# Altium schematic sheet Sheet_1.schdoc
size 456 x 207 mm
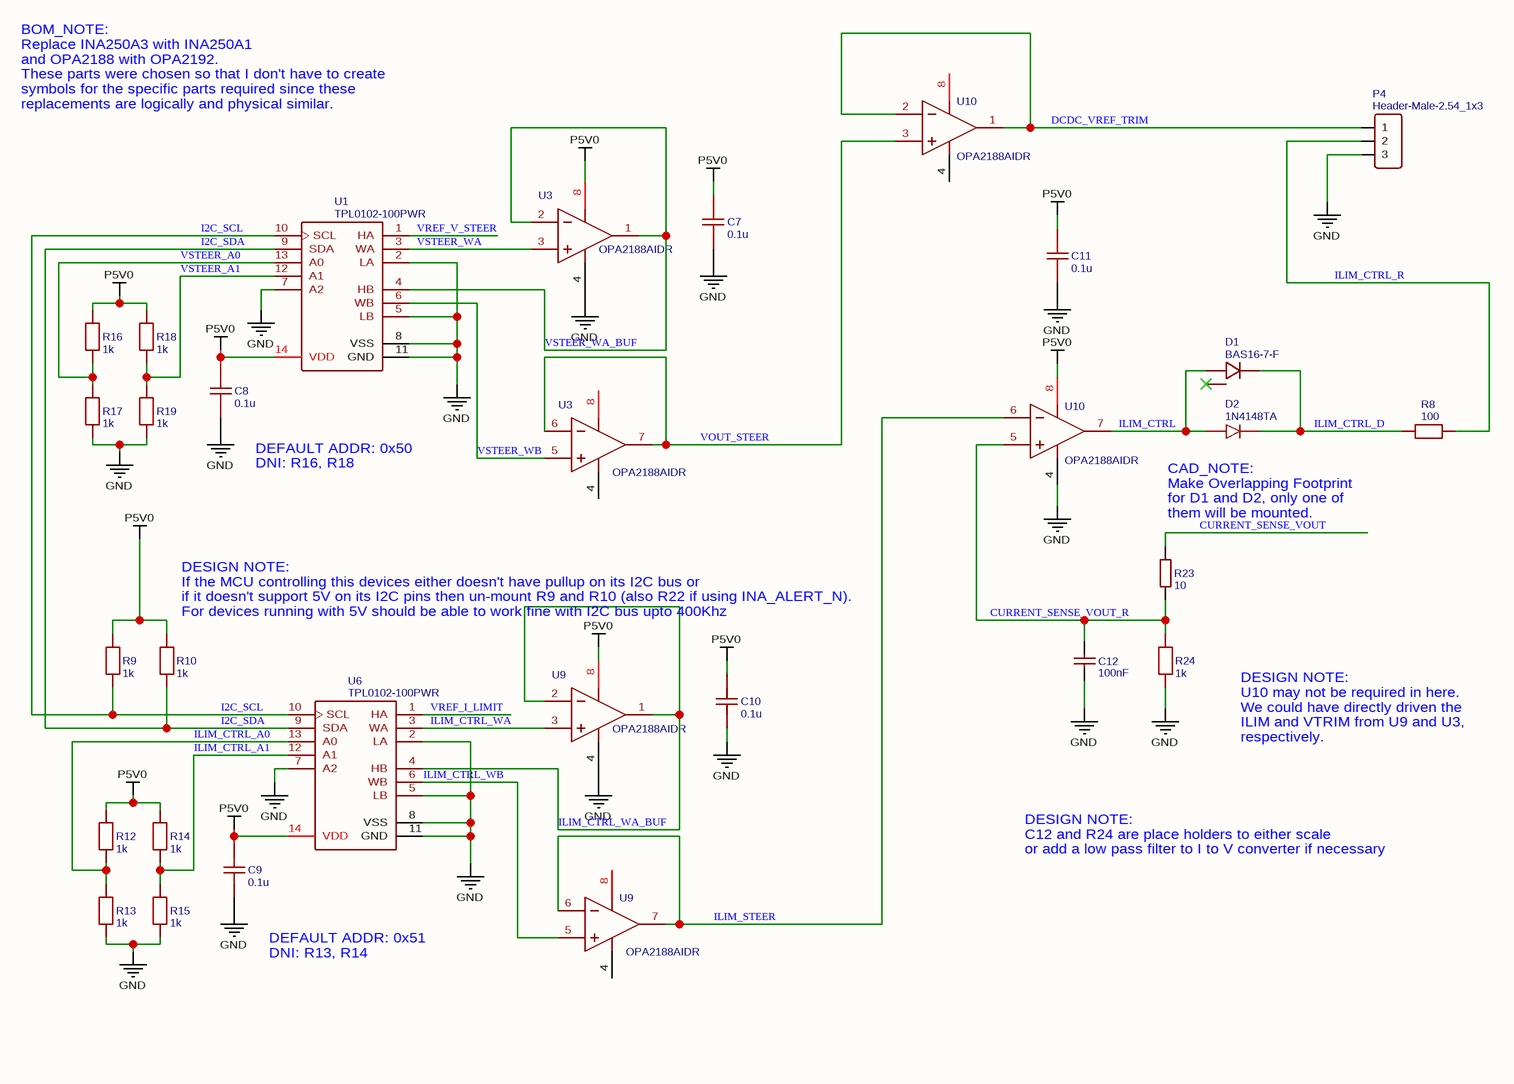
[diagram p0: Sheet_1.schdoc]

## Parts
(Parts that share a designator on the sheet are numbered #1, #2 ... from top to bottom, then left to right.)
C7  0.1u  [0805]
C8  0.1u  [0805]
C9  0.1u  [0805]
C10  0.1u  [0805]
C11  0.1u  [0805]
C12  100nF  [0805]
D1  BAS16-7-F  [SOT-23(SOT-23-3)]
D2  1N4148TA  [DO-35]
P4  Header-Male-2.54_1x3  [HDR-3X1/2.54]
R8  100  [0805]
R9  1k  [0805]
R10  1k  [0805]
R12  1k  [0805]
R13  1k  [0805]
R14  1k  [0805]
R15  1k  [0805]
R16  1k  [0805]
R17  1k  [0805]
R18  1k  [0805]
R19  1k  [0805]
R23  10  [0805]
R24  1k  [0805]
U1  TPL0102-100PWR  [TSSOP-14]
U3#1  OPA2188AIDR  [SOIC-8_150MIL]
U3#2  OPA2188AIDR  [SOIC-8_150MIL]
U6  TPL0102-100PWR  [TSSOP-14]
U9#1  OPA2188AIDR  [SOIC-8_150MIL]
U9#2  OPA2188AIDR  [SOIC-8_150MIL]
U10#1  OPA2188AIDR  [SOIC-8_150MIL]
U10#2  OPA2188AIDR  [SOIC-8_150MIL]

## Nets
GND: C7.1 C8.1 C9.1 C10.1 C11.1 C12.1 P4.3 R13.1 R15.1 R17.1 R19.1 R24.1 U1.2(LA) U1.5(LB) U1.7(A2) U1.8(VSS) U1.11(GND) U3#1.4(V-) U6.2(LA) U6.5(LB) U6.7(A2) U6.8(VSS) U6.11(GND) U9#1.4(V-) U10#2.4(V-)
P5V0: C7.2 C8.2 C9.2 C10.2 C11.2 R9.2 R10.2 R12.2 R14.2 R16.2 R18.2 U1.14(VDD) U3#1.8(V+) U6.14(VDD) U9#1.8(V+) U10#2.8(V+)
CURRENT_SENSE_VOUT: R23.2
CURRENT_SENSE_VOUT_R: C12.2 R23.1 R24.2 U10#2.5(IN_B+)
DCDC_VREF_TRIM: P4.1 U10#1.1(OUT_A) U10#1.2(IN_A-)
I2C_SCL: R9.1 U1.10(SCL) U6.10(SCL)
I2C_SDA: R10.1 U1.9(SDA) U6.9(SDA)
ILIM_CTRL: D1.1(A) D2.1 U10#2.7(OUT_B)
ILIM_CTRL_A0: R12.1 R13.2 U6.13(A0)
ILIM_CTRL_A1: R14.1 R15.2 U6.12(A1)
ILIM_CTRL_D: D1.3(C) D2.2 R8.1
ILIM_CTRL_R: P4.2 R8.2
ILIM_CTRL_WA: U6.3(WA) U9#1.3(IN_A+)
ILIM_CTRL_WA_BUF: U6.4(HB) U9#1.1(OUT_A) U9#1.2(IN_A-)
ILIM_CTRL_WB: U6.6(WB) U9#2.5(IN_B+)
ILIM_STEER: U9#2.6(IN_B-) U9#2.7(OUT_B) U10#2.6(IN_B-)
VOUT_STEER: U3#2.6(IN_B-) U3#2.7(OUT_B) U10#1.3(IN_A+)
VREF_I_LIMIT: U6.1(HA)
VREF_V_STEER: U1.1(HA)
VSTEER_A0: R16.1 R17.2 U1.13(A0)
VSTEER_A1: R18.1 R19.2 U1.12(A1)
VSTEER_WA: U1.3(WA) U3#1.3(IN_A+)
VSTEER_WA_BUF: U1.4(HB) U3#1.1(OUT_A) U3#1.2(IN_A-)
VSTEER_WB: U1.6(WB) U3#2.5(IN_B+)

Not connected (* = marked no-connect by the designer): D1 2*; U3#2 4(V-) 8(V+); U9#2 4(V-) 8(V+); U10#1 4(V-) 8(V+)

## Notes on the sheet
- BOM_NOTE:
  Replace INA250A3 with INA250A1
  and OPA2188 with OPA2192.
  These parts were chosen so that I don't have to create
  symbols for the specific parts required since these
  replacements are logically and physical similar.
- (near C8) DEFAULT ADDR: 0x50
  DNI: R16, R18
- (near R23) CAD_NOTE:
  Make Overlapping Footprint
  for D1 and D2, only one of
  them will be mounted.
- DESIGN NOTE:
  If the MCU controlling this devices either doesn't have pullup on its I2C bus or
  if it doesn't support 5V on its I2C pins then un-mount R9 and R10 (also R22 if using INA_ALERT_N).
  For devices running with 5V should be able to work fine with I2C bus upto 400Khz
- DESIGN NOTE:
  U10 may not be required in here.
  We could have directly driven the
  ILIM and VTRIM from U9 and U3,
  respectively.
- DESIGN NOTE:
  C12 and R24 are place holders to either scale
  or add a low pass filter to I to V converter if necessary
- DEFAULT ADDR: 0x51
  DNI: R13, R14

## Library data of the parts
C7-C11 = 0.1u: nameAlias: Value(F)
C12 = 100nF: BOM_Manufacturer Part: CL21B104JBCNNNC; BOM_Manufacturer: SAMSUNG; nameAlias: Capacitance; SMT Type: Extend; BOM_MOUNT: NO
D1 = BAS16-7-F: BOM_Manufacturer: DIODES; Contributor: LCSC; SMT Type: Extend
D2 = 1N4148TA: BOM_Manufacturer: FAIRCHILD; Contributor: LCSC
P4 = Header-Male-2.54_1x3: BOM_Manufacturer: BOOMELE; BOM_Manufacturer Part: Header2.54mm 1*3P
R8 = 100: nameAlias: Value(Ω)
R9 R10 R12 R15 R17 R19 = 1k: nameAlias: Value(Ω)
R13 R14 R16 R18 R24 = 1k: nameAlias: Value(Ω); BOM_MOUNT: NO
R23 = 10: BOM_Manufacturer: YAGEO; BOM_Manufacturer Part: AC0805FR-0710RL; nameAlias: Resistance (Ohms)
U1 U6 = TPL0102-100PWR: description: 256 Tap Dual Channel Digital Potentiometer with I2C Interface and Non-Volatile Memory, -40 to 85 degC, 14-pin SOP (PW14), Green (RoHS  no SbBr)
U3#1 U9#1 U10#1 = OPA2188AIDR: BOM_Manufacturer: TI; subpart_no: 1; tags: Precision Operational Amplifier
U3#2 U9#2 U10#2 = OPA2188AIDR: BOM_Manufacturer: TI; subpart_no: 2; tags: Precision Operational Amplifier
